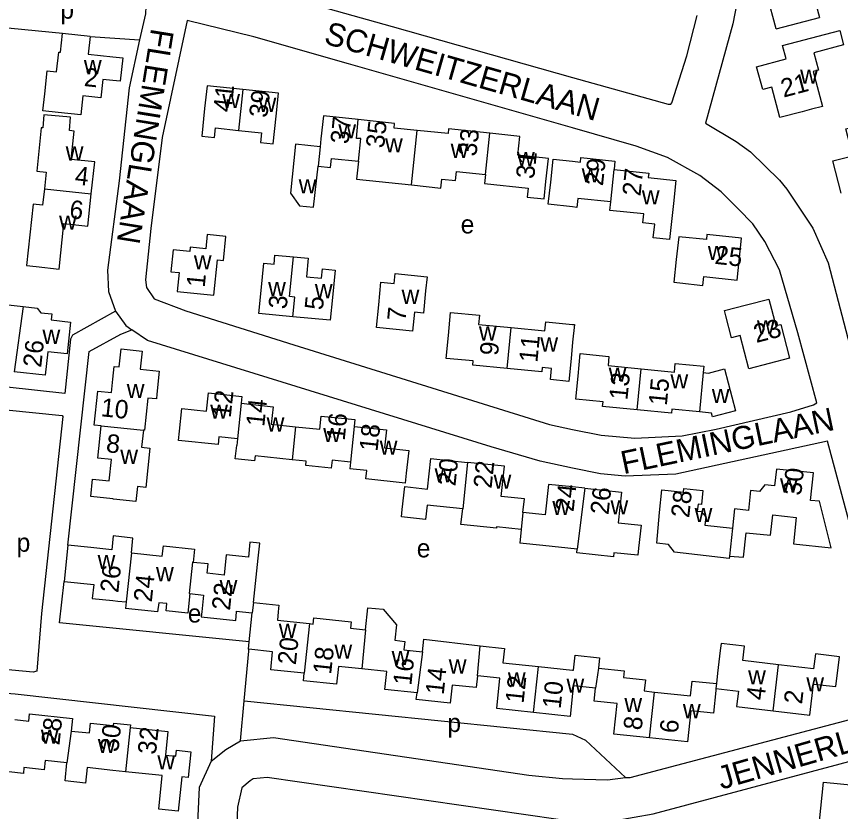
# Model space of a CAD drawing. Extents: x 161093 to 163177, y 379000 to 380904.
# Drawn here: x 162479 to 162658.3, y 380456.5 to 380629.6 of the extents above; entities that cross this region are included whole.
import ezdxf

# ---------------------------------------------------------------- set-up
doc = ezdxf.new("R2010")
doc.units = 0
for name, color, linetype in [('BLT_Basislijn', 7, 'Continuous'), ('BLT_Bebouwing', 7, 'Continuous'), ('BLT_Centroide', 7, 'Continuous'), ('BLT_Huisnummer', 7, 'Continuous'), ('BLT_Onderverdeling_panden', 7, 'Continuous'), ('BLT_Straatnaam', 7, 'Continuous')]:
    doc.layers.add(name, color=color, linetype=linetype)

msp = doc.modelspace()

# ---------------------------------------------------------------- linework, layer by layer
at = {"layer": 'BLT_Basislijn'}
for p, q in [((162531.54, 380635.63), (162560.73, 380627.41)), ((162489, 380625.9), (162439.32, 380630.67)), ((162516.13, 380628.71), (162510.74, 380603.25)), ((162530.65, 380625.19), (162516.13, 380628.71)), ((162624.83, 380621.05), (162627.06, 380629.81)), ((162560.73, 380627.41), (162600, 380616.35)), ((162495.03, 380625.25), (162505.76, 380624.48)), ((162551.23, 380619.29), (162530.65, 380625.19)), ((162621.6, 380610.82), (162624.83, 380621.05)), ((162600, 380605.33), (162551.23, 380619.29)), ((162600, 380616.35), (162620.81, 380610.49)), ((162620.81, 380610.49), (162621.33, 380610.48)), ((162621.33, 380610.48), (162621.6, 380610.82)), ((162613.78, 380601.39), (162600, 380605.33)), ((162510.74, 380603.25), (162508.23, 380583.47)), ((162620.6, 380598.88), (162613.78, 380601.39)), ((162627.64, 380594.96), (162620.6, 380598.88)), ((162632.33, 380591.45), (162627.64, 380594.96)), ((162636, 380587.7), (162632.33, 380591.45)), ((162639.18, 380584.44), (162636, 380587.7)), ((162641.83, 380580.64), (162639.18, 380584.44)), ((162508.23, 380583.47), (162507.05, 380572.29)), ((162644.99, 380574.43), (162641.83, 380580.64)), ((162648.98, 380560.74), (162644.99, 380574.43)), ((162507.05, 380572.29), (162507.33, 380570.58)), ((162507.33, 380570.58), (162508.99, 380568.16)), ((162508.99, 380568.16), (162515.83, 380565.5)), ((162515.83, 380565.5), (162539.38, 380558.13)), ((162653.08, 380545.53), (162648.98, 380560.74)), ((162539.38, 380558.13), (162594.95, 380540.75)), ((162647.44, 380543.56), (162652.39, 380545.06)), ((162652.39, 380545.06), (162653.08, 380545.53)), ((162631.23, 380539.77), (162647.44, 380543.56)), ((162594.95, 380540.75), (162600, 380539.73)), ((162600, 380539.73), (162606.2, 380538.47)), ((162623.82, 380538.31), (162631.23, 380539.77)), ((162606.2, 380538.47), (162613.52, 380537.84)), ((162613.52, 380537.84), (162623.82, 380538.31)), ((162527.74, 380471.9), (162528.53, 380480.6))]:
    msp.add_line(p, q, dxfattribs=at)
for points in [[(162495.33, 380634.77), (162507.15, 380631.74), (162507.1, 380630.16), (162505.76, 380624.48)], [(162635.73, 380632.52), (162634.81, 380628.02), (162628.89, 380606.34), (162635.55, 380602.41), (162638.7, 380600.16), (162645.01, 380593.94), (162646.61, 380592.03), (162652.23, 380583.53), (162655.59, 380576), (162683.93, 380467.29), (162685.9, 380453.19)], [(162505.76, 380624.48), (162503.53, 380614.1), (162501.32, 380593.8), (162498.82, 380574.37), (162499, 380569.75), (162500.53, 380565.43)], [(162500.53, 380565.43), (162491.21, 380560.22), (162490.79, 380559.37), (162489.5, 380547.52), (162437.35, 380553.26), (162437.42, 380558.6)], [(162500.53, 380565.43), (162502.8, 380562.32), (162504.08, 380561.39)], [(162490.2, 380514.54), (162494.81, 380556.67), (162501.72, 380560.41), (162504.08, 380561.39)], [(162611.52, 380463.97), (162612.48, 380463.94), (162614.96, 380464.57), (162670.7, 380479.32), (162668.42, 380488.85), (162655.43, 380537.18), (162622.45, 380529.94), (162611.45, 380529.55), (162606.04, 380530.03), (162600, 380531.3), (162592.93, 380532.79), (162582.27, 380535.94), (162507.49, 380559.04), (162504.08, 380561.39)], [(162469.52, 380533.87), (162470.66, 380544.45), (162470.95, 380544.57), (162488.98, 380542.76), (162489.07, 380542.53), (162484.46, 380499.64), (162483.46, 380487.1), (162482.67, 380486.89), (162464.76, 380488.53)], [(162529.63, 380493.45), (162488.35, 380497.61), (162489.36, 380506.6)], [(162528.53, 380480.6), (162529.53, 380491.46), (162529.58, 380491.87)], [(162459.73, 380472.66), (162467.88, 380478.31), (162468.26, 380482.93), (162478.71, 380482.18), (162522.1, 380477.28), (162521.36, 380467.47)], [(162528.53, 380480.6), (162600, 380473.38), (162602.79, 380472.04), (162611.52, 380463.97)], [(162527.74, 380471.9), (162534.96, 380472.62), (162590.48, 380464.45), (162597.81, 380463.72), (162600, 380463.66), (162607.57, 380463.42), (162611.52, 380463.97)], [(162521.36, 380467.47), (162524.53, 380470.03), (162527.74, 380471.9)], [(162609.26, 380454.6), (162617.51, 380456.01), (162665.48, 380468.91), (162671.67, 380470.27), (162673.04, 380470.08), (162673.82, 380468.82), (162676.14, 380448.82)], [(162521.36, 380467.47), (162518.79, 380461.74), (162516, 380403), (162458.92, 380411.1)], [(162596.86, 380454.78), (162533.53, 380463.97), (162530.49, 380463.64), (162529.85, 380463.23), (162528.06, 380461.67), (162527.07, 380457.49), (162525.61, 380420.58)]]:
    msp.add_lwpolyline(points, dxfattribs=at)
at = {"layer": 'BLT_Bebouwing'}
for p, q in [((162644.28, 380626.88), (162653.67, 380629.39)), ((162495.03, 380625.25), (162489, 380625.9)), ((162527.08, 380537.69), (162526.92, 380536.23)), ((162551.66, 380532.57), (162551.51, 380531.13)), ((162588.79, 380517.94), (162588.48, 380514.95)), ((162490.2, 380514.54), (162489.36, 380506.6)), ((162502.89, 380502.15), (162502.74, 380500.73)), ((162529.63, 380493.45), (162530.3, 380499.77))]:
    msp.add_line(p, q, dxfattribs=at)
for points in [[(162644.28, 380626.88), (162642.33, 380634.24), (162641.18, 380633.93), (162639.32, 380640.96), (162644.15, 380642.24), (162646.91, 380642.98), (162649.86, 380643.76), (162650.8, 380640.22), (162653.67, 380629.39)], [(162654.32, 380610.02), (162651.92, 380609.39), (162649.94, 380608.86), (162645.1, 380607.58), (162643.35, 380614.21), (162641.34, 380613.68), (162640.02, 380618.65), (162646.44, 380620.35), (162645.67, 380623.26), (162658.12, 380626.56)], [(162658.12, 380626.56), (162658.95, 380623.42), (162652.48, 380621.7), (162653.48, 380617.93), (162652.31, 380617.62), (162654.32, 380610.02)], [(162495.03, 380625.25), (162494.62, 380621.4), (162500, 380620.83), (162502.12, 380620.61), (162501.59, 380615.51), (162500, 380615.67), (162497.79, 380615.9), (162497.36, 380611.88), (162493.48, 380612.3), (162493.03, 380608.2), (162488.06, 380608.73), (162484.75, 380609.09), (162485.15, 380612.78), (162485.68, 380617.75), (162487.74, 380617.53), (162488.21, 380621.85), (162488.56, 380621.81), (162489, 380625.9)], [(162528.26, 380613.71), (162520.48, 380614.53), (162519.95, 380609.56), (162519.32, 380603.58), (162522.07, 380603.29), (162522.29, 380605.33), (162527.31, 380604.79)], [(162527.31, 380604.79), (162532.28, 380604.27), (162532.06, 380602.2), (162534.87, 380601.9), (162535.51, 380607.91), (162536.03, 380612.88), (162528.26, 380613.71)], [(162495.29, 380591.01), (162496.04, 380597.94), (162490.89, 380598.49), (162491.55, 380604.66), (162490.53, 380604.77), (162490.77, 380607.7), (162484.99, 380608.17), (162484.77, 380605.34), (162484.42, 380605.37), (162483.41, 380595.95), (162485.48, 380595.73), (162485.09, 380592.11)], [(162553.32, 380607.15), (162545.77, 380607.95), (162545.24, 380602.98), (162545.06, 380601.24)], [(162566.17, 380604.81), (162561.15, 380605.31), (162561.25, 380606.31), (162553.32, 380607.15)], [(162658.42, 380591.15), (162656.63, 380598.16), (162660.96, 380599.27), (162659.46, 380605.17), (162664.28, 380606.4), (162668.62, 380607.5), (162670.95, 380598.38), (162667.02, 380597.37), (162667.98, 380593.59)], [(162581.97, 380604.17), (162572.99, 380605.12), (162572.89, 380604.13), (162566.17, 380604.81)], [(162581.02, 380595.22), (162580.81, 380593.26), (162590.34, 380592.25), (162590.13, 380590.26), (162593.8, 380589.87), (162594.2, 380593.7), (162594.73, 380598.68), (162588.04, 380599.38), (162588.48, 380603.48), (162581.97, 380604.17)], [(162545.06, 380601.24), (162539.73, 380601.81), (162538.6, 380591.17), (162540.58, 380588.4), (162543.66, 380588.07), (162544.61, 380596.98)], [(162544.61, 380596.98), (162547.29, 380596.7), (162547.51, 380598.72), (162553.39, 380598.1)], [(162553.39, 380598.1), (162552.98, 380594.18), (162564.91, 380592.92)], [(162608.27, 380589.22), (162601.14, 380589.98), (162600.94, 380588.05), (162600, 380588.15), (162594.7, 380588.71), (162595.22, 380593.56), (162595.74, 380598.53), (162600, 380598.08), (162601.71, 380597.9), (162601.81, 380598.91), (162609.21, 380598.13), (162609.02, 380596.3)], [(162609.02, 380596.3), (162616.55, 380595.5), (162616.45, 380594.53), (162622.45, 380593.89), (162621.93, 380588.92), (162621.09, 380581.06), (162617.53, 380581.44), (162617.85, 380584.4), (162615.26, 380584.67), (162615.46, 380586.61), (162608.07, 380587.39), (162608.27, 380589.22)], [(162564.91, 380592.92), (162571.33, 380592.24), (162571.53, 380594.2), (162574.49, 380593.89), (162574.7, 380595.89), (162581.02, 380595.22)], [(162485.09, 380592.11), (162484.7, 380588.49), (162482.67, 380588.71), (162481.23, 380575.37), (162483.3, 380575.15), (162488.27, 380574.61), (162489.34, 380584.5), (162494.53, 380583.95), (162495.29, 380591.01)], [(162520.21, 380579.02), (162516.8, 380579.35), (162516.71, 380578.43), (162513.08, 380578.78), (162512.62, 380574.02), (162514.38, 380573.84), (162513.98, 380569.75), (162521.98, 380568.97), (162522.73, 380576.66), (162524.07, 380576.5), (162524.58, 380581.74), (162520.51, 380582.14), (162520.21, 380579.02)], [(162623.33, 380571.6), (162628.3, 380571.07), (162628.51, 380572.99), (162635.78, 380572.21), (162636.75, 380581.32), (162629.21, 380582.12), (162629.09, 380581.02), (162623.08, 380581.65), (162622.55, 380576.68), (162622.03, 380571.73), (162623.33, 380571.6)], [(162539.13, 380564.25), (162531.75, 380564.97), (162532.24, 380569.95), (162532.82, 380575.93), (162535.04, 380575.71), (162535.23, 380577.67), (162539.25, 380577.28)], [(162539.25, 380577.28), (162542.49, 380576.96), (162542.09, 380572.92), (162545.36, 380572.6), (162545.56, 380574.68), (162548.33, 380574.41), (162547.75, 380568.43), (162547.26, 380563.46), (162539.13, 380564.25)], [(162568.02, 380569.9), (162567.55, 380565.05), (162565.57, 380565.24), (162565.17, 380561.11), (162557.32, 380561.88), (162557.81, 380566.85), (162558.29, 380571.78), (162561.2, 380571.5), (162561.4, 380573.62), (162568.32, 380572.95), (162568.02, 380569.9)], [(162466.75, 380565.65), (162468.64, 380565.44), (162468.88, 380567.63), (162470.7, 380569.09), (162475.13, 380568.61), (162476.53, 380566.88), (162480.49, 380566.45)], [(162637.85, 380566.83), (162642.69, 380568.09), (162644.2, 380562.3), (162645.25, 380562.57), (162647.15, 380555.24), (162638.31, 380552.93), (162636.44, 380560.12), (162634.56, 380559.63), (162633.3, 380564.47), (162633.01, 380565.57), (162637.85, 380566.83)], [(162480.49, 380566.45), (162483.49, 380566.13), (162484.31, 380565.12), (162486.7, 380564.86), (162486.56, 380563.57), (162490.79, 380563.03), (162490.05, 380556.15), (162485.81, 380556.61), (162485.26, 380551.5), (162478.54, 380552.23)], [(162585.76, 380552.95), (162578.26, 380553.68), (162578.35, 380554.61), (162572.49, 380555.18), (162572.97, 380560.16), (162573.46, 380565.17), (162579.71, 380564.56), (162579.51, 380562.58), (162586.63, 380561.88)], [(162586.63, 380561.88), (162593.95, 380561.17), (162594.15, 380563.13), (162600, 380562.56), (162600.38, 380562.53), (162600, 380558.68), (162599.65, 380555.15), (162599.17, 380550.17), (162595.15, 380550.56), (162595.39, 380553), (162593.35, 380553.2), (162593.26, 380552.22), (162585.76, 380552.95)], [(162497.46, 380540.48), (162495.92, 380540.65), (162496.7, 380548.07), (162499.69, 380547.75), (162500, 380550.65), (162500.29, 380553.43), (162501.36, 380553.32), (162501.78, 380557.28), (162506.33, 380556.78), (162505.91, 380552.81), (162510.08, 380552.37), (162509.55, 380547.4), (162509.44, 380546.35), (162507.6, 380546.55), (162506.86, 380539.54), (162506.62, 380539.52)], [(162614.02, 380543.95), (162606.51, 380544.68), (162606.61, 380545.72), (162600.7, 380546.3), (162601.18, 380551.28), (162601.66, 380556.23), (162607.9, 380555.62), (162607.7, 380553.62), (162614.89, 380552.92)], [(162614.89, 380552.92), (162622.14, 380552.21), (162622.32, 380554.06), (162628.54, 380553.46), (162628.41, 380552.1)], [(162628.41, 380552.1), (162629.57, 380551.99), (162633.06, 380552.89), (162635.43, 380543.78), (162630.41, 380542.47), (162630.2, 380543.28), (162627.57, 380543.51)], [(162527.08, 380537.69), (162523.04, 380538.11), (162522.86, 380536.41), (162514.29, 380537.32), (162514.5, 380539.32), (162515.02, 380544.29), (162520.37, 380543.72), (162520.79, 380547.68), (162528.05, 380546.91), (162527.89, 380545.4)], [(162527.89, 380545.4), (162534.85, 380544.66), (162534.45, 380540.86), (162539.71, 380540.3)], [(162627.57, 380543.51), (162621.61, 380544.1), (162621.52, 380543.22), (162614.02, 380543.95)], [(162539.71, 380540.3), (162544.99, 380539.75), (162545.29, 380542.61), (162552.63, 380541.84), (162552.48, 380540.36)], [(162506.62, 380539.52), (162506.23, 380535.84), (162508.02, 380535.65), (162507.12, 380527.1), (162505.33, 380527.28), (162504.99, 380524.04), (162500.13, 380524.55), (162500, 380524.57), (162495.16, 380525.08), (162495.56, 380528.89), (162499.18, 380528.5), (162499.68, 380533.17), (162496.73, 380533.48), (162497.46, 380540.48)], [(162552.48, 380540.36), (162559.51, 380539.62), (162559.09, 380535.7), (162564.33, 380535.14), (162563.81, 380530.17), (162563.58, 380528.03), (162555.03, 380528.93), (162555.22, 380530.74), (162551.51, 380531.13)], [(162538.96, 380533.11), (162530.92, 380533.96), (162530.8, 380532.84), (162526.61, 380533.28), (162526.92, 380536.23)], [(162576.09, 380522.41), (162568.35, 380523.22), (162568.02, 380520.11), (162562.77, 380520.66), (162562.94, 380522.29), (162563.46, 380527.26), (162568.46, 380526.73), (162569.16, 380533.39), (162577.16, 380532.54)], [(162551.66, 380532.57), (162547.66, 380532.99), (162547.48, 380531.25), (162541.95, 380531.84), (162542.05, 380532.79), (162538.96, 380533.11)], [(162589.18, 380521.6), (162589.5, 380524.6), (162584.46, 380525.13), (162585.16, 380531.7), (162577.16, 380532.54)], [(162637.73, 380517.17), (162643.05, 380516.66), (162643.51, 380521.09), (162648.63, 380520.55), (162648.03, 380514.81), (162656.27, 380513.94), (162653.68, 380524.07), (162651.77, 380524.27), (162652.4, 380530.24), (162644.31, 380531.09), (162643.92, 380527.41), (162641.84, 380527.62), (162640.68, 380526.23), (162638.7, 380526.43), (162638.24, 380522.09), (162635.23, 380522.41), (162634.78, 380518.2)], [(162602.65, 380526.91), (162600, 380527.19), (162594.72, 380527.75), (162594.02, 380521.09), (162589.18, 380521.6)], [(162602.65, 380526.91), (162610.59, 380526.08), (162609.88, 380519.4), (162614.88, 380518.88), (162614.35, 380513.9), (162614.18, 380512.33), (162608.99, 380512.88), (162608.9, 380512.01), (162600.88, 380512.84), (162600.96, 380513.63)], [(162634.14, 380512.15), (162634.08, 380511.59), (162622.19, 380512.96), (162620.87, 380514.66), (162618.29, 380514.95), (162618.9, 380521.62), (162619.42, 380526.59), (162624.14, 380526.09), (162624.22, 380526.83), (162628.34, 380526.4), (162628.02, 380523.36), (162627.27, 380523.44), (162627.11, 380521.91), (162627.93, 380521.82), (162628.96, 380520.71), (162628.76, 380518.84), (162634.78, 380518.2)], [(162588.79, 380517.94), (162583.43, 380518.51), (162583.4, 380518.23), (162575.67, 380519.04), (162576.09, 380522.41)], [(162504.02, 380512.83), (162504.34, 380516.04), (162500.07, 380516.54), (162499.75, 380513.53), (162495.17, 380514.01), (162490.2, 380514.54)], [(162634.14, 380512.15), (162637.13, 380511.87), (162637.73, 380517.17)], [(162504.02, 380512.83), (162510.73, 380512.13), (162510.97, 380514.4), (162517.77, 380513.68), (162517.46, 380510.76)], [(162530.6, 380502.06), (162531.62, 380511.66), (162531.96, 380514.96), (162529.8, 380515.19), (162529.45, 380511.89), (162524.65, 380512.4), (162524.19, 380508.02), (162520.51, 380508.41), (162520.72, 380510.42), (162517.46, 380510.76)], [(162600.96, 380513.63), (162593.54, 380514.41), (162588.48, 380514.95)], [(162489.36, 380506.6), (162495.83, 380505.92), (162495.51, 380502.93), (162500, 380502.45), (162501.07, 380502.34), (162502.89, 380502.15)], [(162516.73, 380503.97), (162516.28, 380499.73), (162511.57, 380500.23), (162511.74, 380501.81), (162509.95, 380501.99), (162509.7, 380500), (162502.74, 380500.73)], [(162516.73, 380503.97), (162519.68, 380503.65), (162519.3, 380500), (162519.18, 380498.95), (162526.7, 380498.15), (162526.9, 380500), (162526.91, 380500.13), (162528.18, 380500), (162530.3, 380499.77)], [(162530.6, 380502.06), (162536.12, 380501.48), (162535.96, 380500), (162535.76, 380498.18), (162542.77, 380497.44)], [(162554.96, 380496.12), (162555.47, 380500.9), (162558.76, 380500.55), (162561.65, 380497.15), (162561.3, 380493.81), (162563.49, 380493.58), (162563.3, 380491.76), (162567.31, 380491.33)], [(162542.77, 380497.44), (162543.57, 380497.35), (162543.72, 380498.7), (162551.8, 380497.84), (162551.65, 380496.47), (162554.96, 380496.12)], [(162567.31, 380491.33), (162567.65, 380494.04), (162579.86, 380492.61)], [(162529.58, 380491.87), (162529.46, 380491.88), (162529.63, 380493.45)], [(162579.86, 380492.61), (162585.17, 380492.05), (162584.84, 380488.93), (162592.54, 380488.12)], [(162644.8, 380488.49), (162637, 380489.41), (162637.37, 380492.52), (162632.29, 380493.12), (162632.11, 380491.6), (162631.53, 380486.63), (162631.29, 380484.38)], [(162541.62, 380486.64), (162534.31, 380487.41), (162534.73, 380491.32), (162529.58, 380491.87)], [(162592.54, 380488.12), (162600, 380487.32), (162600.17, 380487.3), (162600.51, 380490.56), (162605.83, 380490), (162605.59, 380487.73)], [(162643.63, 380478.47), (162651.59, 380477.54), (162652.39, 380484.29), (162657.27, 380483.72), (162658.03, 380490.22), (162652.8, 380490.84), (162652.42, 380487.6), (162644.8, 380488.49)], [(162554.16, 380487.58), (162549.06, 380488.13), (162548.64, 380484.25), (162541.45, 380485.01), (162541.62, 380486.64)], [(162566.14, 380482.38), (162559.16, 380483.11), (162559.57, 380487.01), (162554.16, 380487.58)], [(162605.59, 380487.73), (162611.18, 380487.13), (162611.03, 380485.74), (162615.81, 380485.23), (162615.55, 380482.79), (162617.79, 380482.55)], [(162579.27, 380486.08), (162578.99, 380483.52), (162573.77, 380484.07), (162573.35, 380480.16), (162565.99, 380480.94), (162566.14, 380482.38)], [(162591.48, 380478.1), (162583.49, 380478.95), (162584.19, 380485.56), (162579.27, 380486.08)], [(162617.79, 380482.55), (162625.66, 380481.72), (162626, 380484.94), (162631.29, 380484.38)], [(162605, 380483.39), (162600.18, 380483.91), (162600, 380482.26), (162599.47, 380477.25), (162591.48, 380478.1)], [(162616.69, 380472.57), (162608.94, 380473.4), (162609.65, 380480.04), (162604.7, 380480.57), (162605, 380483.39)], [(162631.18, 380483.29), (162631.14, 380482.9), (162630.61, 380477.93), (162625.69, 380478.45), (162624.97, 380471.69), (162616.69, 380472.57)], [(162631.18, 380483.29), (162636.05, 380482.73), (162635.66, 380479.41), (162643.63, 380478.47)], [(162478.63, 380476.57), (162481.72, 380476.24), (162481.88, 380477.77), (162491.23, 380476.79), (162490.93, 380474.06)], [(162490.93, 380474.06), (162494.87, 380473.65), (162495.09, 380475.76), (162500, 380475.25), (162500.12, 380475.24), (162500.18, 380475.8), (162503.79, 380475.42), (162503.72, 380474.82)], [(162503.72, 380474.82), (162511.96, 380473.94), (162511.41, 380468.82), (162513.7, 380468.58), (162513.84, 380469.87), (162516.97, 380469.54), (162516.37, 380463.91), (162514.97, 380464.06), (162514.18, 380456.61), (162509.95, 380457.06), (162510.73, 380464.35), (162502.7, 380465.21)], [(162490, 380467.14), (162485.25, 380467.64), (162485.04, 380465.63), (162480.65, 380466.1), (162480.52, 380464.84), (162477.37, 380465.18)], [(162502.7, 380465.21), (162500, 380465.5), (162494.39, 380466.09), (162494.04, 380462.74), (162489.58, 380463.21), (162490, 380467.14)], [(162654.55, 380462.94), (162661.98, 380462.22), (162662.11, 380463.63), (162669.14, 380462.95), (162668.35, 380454.81), (162664.85, 380455.15), (162664.68, 380453.35), (162653.72, 380454.41), (162654.55, 380462.94)]]:
    msp.add_lwpolyline(points, dxfattribs=at)
at = {"layer": 'BLT_Onderverdeling_panden'}
for p, q in [((162528.26, 380613.71), (162527.31, 380604.79)), ((162564.91, 380592.92), (162566.17, 380604.81)), ((162581.02, 380595.22), (162581.97, 380604.17)), ((162545.06, 380601.24), (162544.61, 380596.98)), ((162608.27, 380589.22), (162609.02, 380596.3)), ((162485.09, 380592.11), (162495.29, 380591.01)), ((162480.49, 380566.45), (162478.54, 380552.23)), ((162585.76, 380552.95), (162586.63, 380561.88)), ((162614.02, 380543.95), (162614.89, 380552.92)), ((162628.41, 380552.1), (162627.57, 380543.51)), ((162527.89, 380545.4), (162527.08, 380537.69)), ((162497.46, 380540.48), (162506.62, 380539.52)), ((162539.71, 380540.3), (162538.96, 380533.11)), ((162552.48, 380540.36), (162551.66, 380532.57)), ((162577.16, 380532.54), (162576.09, 380522.41)), ((162602.65, 380526.91), (162600.96, 380513.63)), ((162589.18, 380521.6), (162588.79, 380517.94)), ((162634.78, 380518.2), (162634.14, 380512.15)), ((162504.02, 380512.83), (162502.89, 380502.15)), ((162530.6, 380502.06), (162530.3, 380499.77)), ((162542.77, 380497.44), (162541.62, 380486.64)), ((162554.96, 380496.12), (162554.16, 380487.58)), ((162579.27, 380486.08), (162579.86, 380492.61)), ((162567.31, 380491.33), (162566.14, 380482.38)), ((162591.48, 380478.1), (162592.54, 380488.12)), ((162605.59, 380487.73), (162605, 380483.39)), ((162643.63, 380478.47), (162644.8, 380488.49)), ((162616.69, 380472.57), (162617.79, 380482.55)), ((162503.72, 380474.82), (162502.7, 380465.21)), ((162490.93, 380474.06), (162490, 380467.14))]:
    msp.add_line(p, q, dxfattribs=at)
for points in [[(162553.39, 380598.1), (162553.91, 380603.04), (162552.95, 380603.05), (162553.32, 380607.15)], [(162539.13, 380564.25), (162539.53, 380568.48), (162538.4, 380568.65), (162539.25, 380577.28)], [(162517.46, 380510.76), (162517.31, 380510.82), (162516.58, 380503.97), (162516.73, 380503.97)], [(162631.29, 380484.38), (162631.18, 380483.29)]]:
    msp.add_lwpolyline(points, dxfattribs=at)

# ---------------------------------------------------------------- texts
at = {"layer": 'BLT_Centroide'}
for s, p in [('p', (162488.56, 380629.12)), ('w', (162493.68, 380617.03)), ('w', (162649.48, 380614.95)), ('w', (162523.78, 380609.67)), ('w', (162531.67, 380608.84)), ('w', (162549.03, 380603.08)), ('w', (162559.19, 380600.03)), ('w', (162573.47, 380598.81)), ('w', (162489.72, 380598.23)), ('w', (162587.88, 380597.03)), ('w', (162601.96, 380593.47)), ('w', (162540.4, 380591.1)), ('w', (162615.05, 380588.69)), ('w', (162488.27, 380583.2)), ('e', (162575.64, 380582.37)), ('w', (162629.4, 380576.59)), ('w', (162517.6, 380574.56)), ('w', (162533.75, 380568.74)), ('w', (162543.92, 380568.27)), ('w', (162562.79, 380567.03)), ('w', (162579.61, 380559.06)), ('w', (162640.08, 380560.41)), ('w', (162484.67, 380558.33)), ('w', (162592.96, 380556.66)), ('w', (162607.84, 380550.09)), ('w', (162621.27, 380548.62)), ('w', (162503, 380546.52)), ('w', (162630.27, 380545.47)), ('w', (162521.16, 380542.03)), ('w', (162533.43, 380539.25)), ('w', (162545.74, 380536.94)), ('w', (162558.03, 380534.19)), ('w', (162501.59, 380532.22)), ('w', (162569.97, 380528.19)), ('w', (162582.8, 380526.81)), ('w', (162645.12, 380525.97)), ('w', (162595.58, 380521.09)), ('w', (162608.23, 380521.22)), ('w', (162626.53, 380519.53)), ('p', (162479.05, 380513.09)), ('e', (162566.09, 380511.86)), ('w', (162496.66, 380509.34)), ('w', (162509.37, 380506.66)), ('w', (162523.2, 380503.86)), ('e', (162516.28, 380497.68)), ('w', (162536.08, 380494.34)), ('w', (162548.18, 380489.81)), ('w', (162560.62, 380488.41)), ('w', (162573.05, 380486.56)), ('w', (162585.91, 380483.75)), ('w', (162638.17, 380484.2)), ('w', (162598.66, 380482.41)), ('w', (162650.83, 380482.7)), ('w', (162611.25, 380478.2)), ('w', (162623.98, 380476.84)), ('p', (162572.75, 380473.85)), ('w', (162484.3, 380471.31)), ('w', (162496.7, 380469.28)), ('w', (162509.66, 380465.72))]:
    msp.add_text(s, height=4, dxfattribs=at).set_placement(p)
at = {"layer": 'BLT_Huisnummer'}
for s, rotation, p in [('2', 353.8572, (162493.6, 380614.48)), ('21', 14.842, (162645.87, 380611.93)), ('41', 83.9542, (162525.77, 380608.65)), ('39', 83.9498, (162533.56, 380607.45)), ('37', 83.9469, (162551.24, 380601.71)), ('35', 83.9471, (162558.96, 380600.83)), ('33', 83.9507, (162579.05, 380599.04)), ('31', 83.9496, (162591.61, 380594.14)), ('29', 83.9565, (162606.58, 380592.6)), ('4', 353.8546, (162491.59, 380593.07)), ('27', 83.9512, (162614.74, 380590.38)), ('6', 353.8572, (162490.39, 380585.7)), ('25', 353.9504, (162630.78, 380575.77)), ('1', 84.4211, (162519.95, 380570.5)), ('3', 84.4237, (162537.77, 380565.79)), ('5', 84.4228, (162545.65, 380565.59)), ('7', 84.4241, (162563.61, 380563.16)), ('23', 14.5882, (162639.94, 380558.52)), ('26', 83.8421, (162484.38, 380553.07)), ('9', 84.4235, (162583.75, 380555.66)), ('11', 84.4228, (162592.31, 380554.15)), ('13', 84.421, (162611.9, 380546)), ('15', 84.4228, (162620.47, 380544.78)), ('12', 83.977, (162525.61, 380542.13)), ('10', 353.9754, (162497.24, 380542.6)), ('14', 83.9889, (162532.9, 380540.21)), ('16', 83.9781, (162550.39, 380537.16)), ('18', 83.9724, (162557.54, 380534.81)), ('8', 353.9757, (162498.38, 380534.79)), ('20', 83.9807, (162574.49, 380527.27)), ('22', 83.976, (162582.35, 380526.75)), ('30', 83.9766, (162649.71, 380525.21)), ('24', 83.9789, (162600.19, 380521.67)), ('26', 83.9794, (162607.79, 380521.03)), ('28', 83.9496, (162625.34, 380520.35)), ('26', 83.9765, (162501.16, 380504.05)), ('24', 83.9736, (162508.44, 380502.02)), ('22', 83.9764, (162525.45, 380500.2)), ('20', 83.9297, (162539.77, 380488.34)), ('18', 83.9331, (162547.45, 380486.27)), ('16', 83.9346, (162564.9, 380483.87)), ('14', 83.9251, (162571.94, 380481.84)), ('12', 83.9279, (162589.31, 380479.97)), ('10', 83.9244, (162597.38, 380478.79)), ('4', 83.2935, (162641.71, 380480.62)), ('2', 83.3015, (162649.88, 380479.78)), ('28', 83.9613, (162488.35, 380470.87)), ('8', 83.9307, (162614.99, 380474.12)), ('6', 83.9231, (162622.87, 380473.44)), ('30', 83.9026, (162501.17, 380469.4)), ('32', 83.8961, (162509.33, 380468.82))]:
    msp.add_text(s, height=4, rotation=rotation, dxfattribs=at).set_placement(p)
at = {"layer": 'BLT_Straatnaam'}
for s, rotation, p in [('FLEMINGLAAN', 260.8297, (162508.34, 380627.18)), ('SCHWEITZERLAAN', 344.0437, (162545.68, 380623.78)), ('FLEMINGLAAN', 11.8748, (162611.07, 380529.94)), ('JENNERLAAN', 16.1277, (162632.34, 380461.27))]:
    msp.add_text(s, height=5, rotation=rotation, dxfattribs=at).set_placement(p)

doc.saveas('drawing.dxf')
